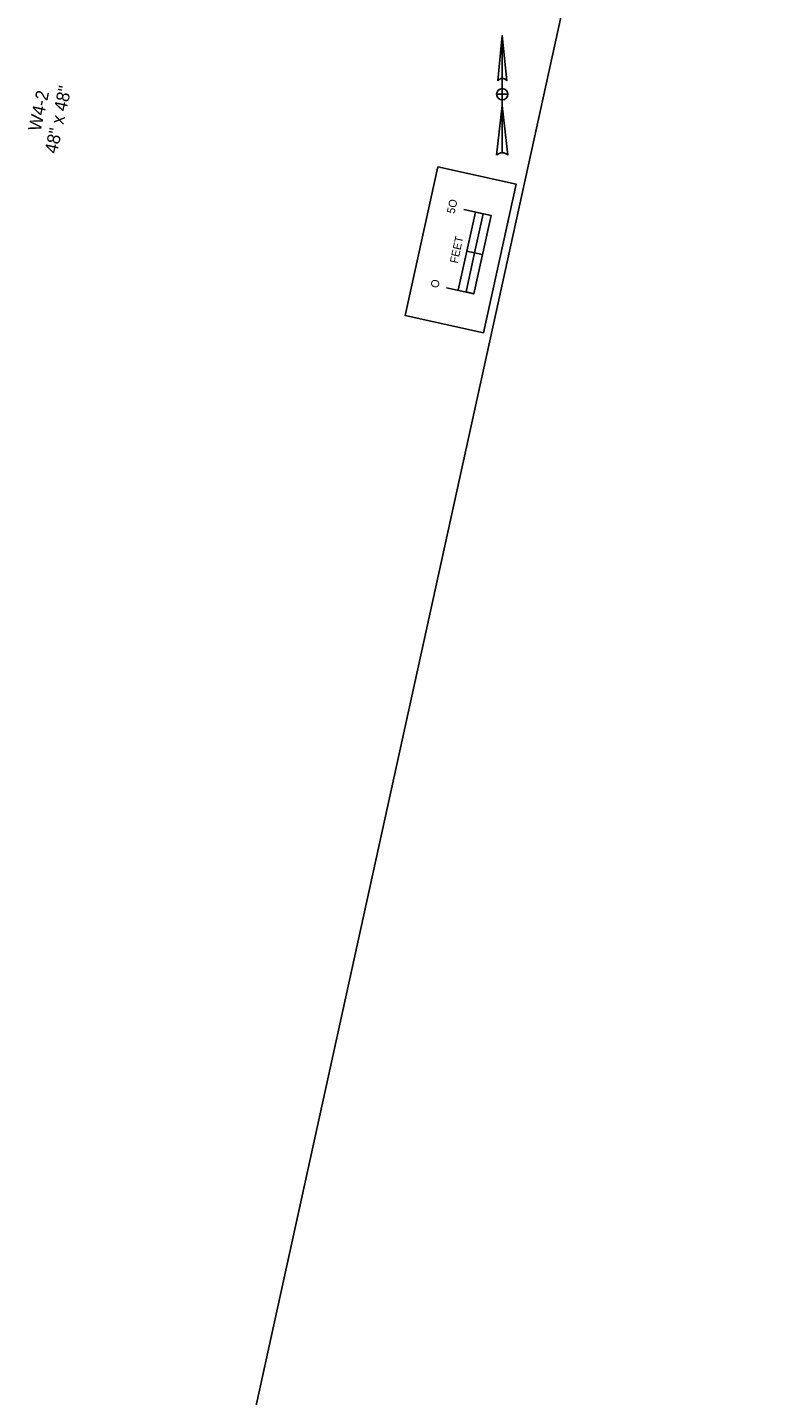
# Model space of a CAD drawing. Extents: x 14104283 to 14120882, y 8635219 to 8671666.
# Drawn here: x 14107780 to 14108248, y 8637146 to 8638001 of the extents above; entities that cross this region are included whole.
import ezdxf

# ---------------------------------------------------------------- set-up
doc = ezdxf.new("R2010")
doc.units = 0
for name, color, linetype in [('Cell', 7, 'Continuous'), ('dsnCellsNorthArrow', 7, 'Continuous'), ('dsnCellsScaleBlock', 7, 'Continuous'), ('dsnNonPlotable', 7, 'Continuous')]:
    doc.layers.add(name, color=color, linetype=linetype)

msp = doc.modelspace()

# ---------------------------------------------------------------- linework, layer by layer
at = {"layer": 'dsnCellsNorthArrow'}
for p, q in [((14108076.38, 8637995.68), (14108079.2, 8637967.51)), ((14108076.38, 8637995.68), (14108076.38, 8637922.44)), ((14108073.57, 8637967.51), (14108073.56, 8637967.51)), ((14108073.67, 8637967.78), (14108074.2, 8637968.36)), ((14108076.38, 8637955.54), (14108076.38, 8637955.54)), ((14108072.86, 8637921.03), (14108076.38, 8637952.02))]:
    msp.add_line(p, q, dxfattribs=at)
for points in [[(14108073.56, 8637967.51), (14108076.38, 8637995.68), (14108076.38, 8637968.92)], [(14108079.9, 8637959.06), (14108076.38, 8637959.06), (14108076.38, 8637962.59)], [(14108076.38, 8637955.54), (14108076.38, 8637959.06), (14108072.86, 8637959.06)], [(14108076.38, 8637922.44), (14108076.38, 8637952.02), (14108079.9, 8637921.03)]]:
    msp.add_lwpolyline(points, dxfattribs=at)
for centre, radius, start, end in [((14108076.38, 8637959.06), 3.52, 90, 180), ((14108076.38, 8637965.4), 3.52, 90.02039, 143.12574), ((14108076.38, 8637965.4), 3.52, 36.84806, 90.02184), ((14108076.38, 8637959.06), 3.52, 0, 90), ((14108076.38, 8637959.06), 3.52, 180, 270), ((14108076.38, 8637959.06), 3.52, 270, 360), ((14108076.38, 8637917.34), 5.1, 89.98939, 133.61895), ((14108076.38, 8637917.33), 5.11, 46.40206, 90.00064)]:
    msp.add_arc(centre, radius, start, end, dxfattribs=at)
at = {"layer": 'dsnCellsScaleBlock'}
msp.add_line((14108064.01, 8637858.86), (14108054.24, 8637861.01), dxfattribs=at)
msp.add_line((14108064.01, 8637858.86), (14108054.24, 8637861.01), dxfattribs=at)
for points in [[(14108064.56, 8637810.11), (14108015.73, 8637820.84), (14108036.11, 8637913.63), (14108084.95, 8637902.9)], [(14108015.73, 8637820.84), (14108036.11, 8637913.63), (14108084.95, 8637902.9), (14108064.56, 8637810.11)], [(14108064.56, 8637810.11), (14108015.73, 8637820.84), (14108036.11, 8637913.63), (14108084.95, 8637902.9)], [(14108059.09, 8637859.94), (14108064.46, 8637884.36), (14108059.61, 8637885.43), (14108054.24, 8637861.01)], [(14108058.65, 8637834.45), (14108064.01, 8637858.86), (14108059.09, 8637859.94), (14108053.73, 8637835.53)]]:
    msp.add_lwpolyline(points, close=True, dxfattribs=at)
for points in [[(14108041.55, 8637838.2), (14108058.65, 8637834.45), (14108069.38, 8637883.28), (14108052.28, 8637887.04)], [(14108048.88, 8637836.59), (14108059.61, 8637885.43)]]:
    msp.add_lwpolyline(points, dxfattribs=at)
at = {"layer": 'dsnNonPlotable'}
msp.add_lwpolyline([(14106924.98, 8637306.69), (14107261.36, 8638837.67), (14108247.83, 8638620.92), (14107911.44, 8637089.94)], close=True, dxfattribs=at)

# ---------------------------------------------------------------- texts
at = {"layer": 'Cell'}
for s, p in [('48" x 48"', (14107798.04, 8637921.53)), ('W4-2', (14107787.78, 8637935.44))]:
    msp.add_text(s, height=8, rotation=77.61021, dxfattribs=at).set_placement(p)
at = {"layer": 'dsnCellsScaleBlock'}
for s, p in [('5O', (14108046.52, 8637884.13)), ('FEET', (14108048.41, 8637853.1)), ('O', (14108036.32, 8637837.68))]:
    msp.add_text(s, height=5, rotation=77.60784, dxfattribs=at).set_placement(p)

doc.saveas('drawing.dxf')
